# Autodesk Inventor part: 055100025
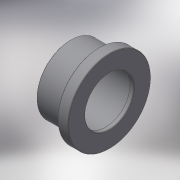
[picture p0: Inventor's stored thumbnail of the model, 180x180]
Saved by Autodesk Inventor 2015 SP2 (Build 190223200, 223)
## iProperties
Created: 2017-10
Part Number: 055100025
Material: Generic
Description: PLASSON FLANGE FLAT AD.-CEM 25
Document SubType Name: Modeling
Designer: KIM
Mass: 11.545 g
Surface Area: 59.5153 cm^2
Volume: 11.545 cm^3
Density: 1 g/cm^3
Appearance: Default
Author: KIM
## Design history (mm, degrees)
derived "055100.ipt"
feature "Solid1::055100.ipt"
tag "TaggingFeature1"
body "Solid1"
other parameters: "d0" = 22, "d1" = 33, "d2" = 25, "d3" = 22.5, "d4" = 7, "d5" = 19, "d6" = 41, "d8" = 0.25, "d_" = 25, "E_" = 33, "E_1" = 41, "l_" = 19, "B_" = 7, "H_" = 22
